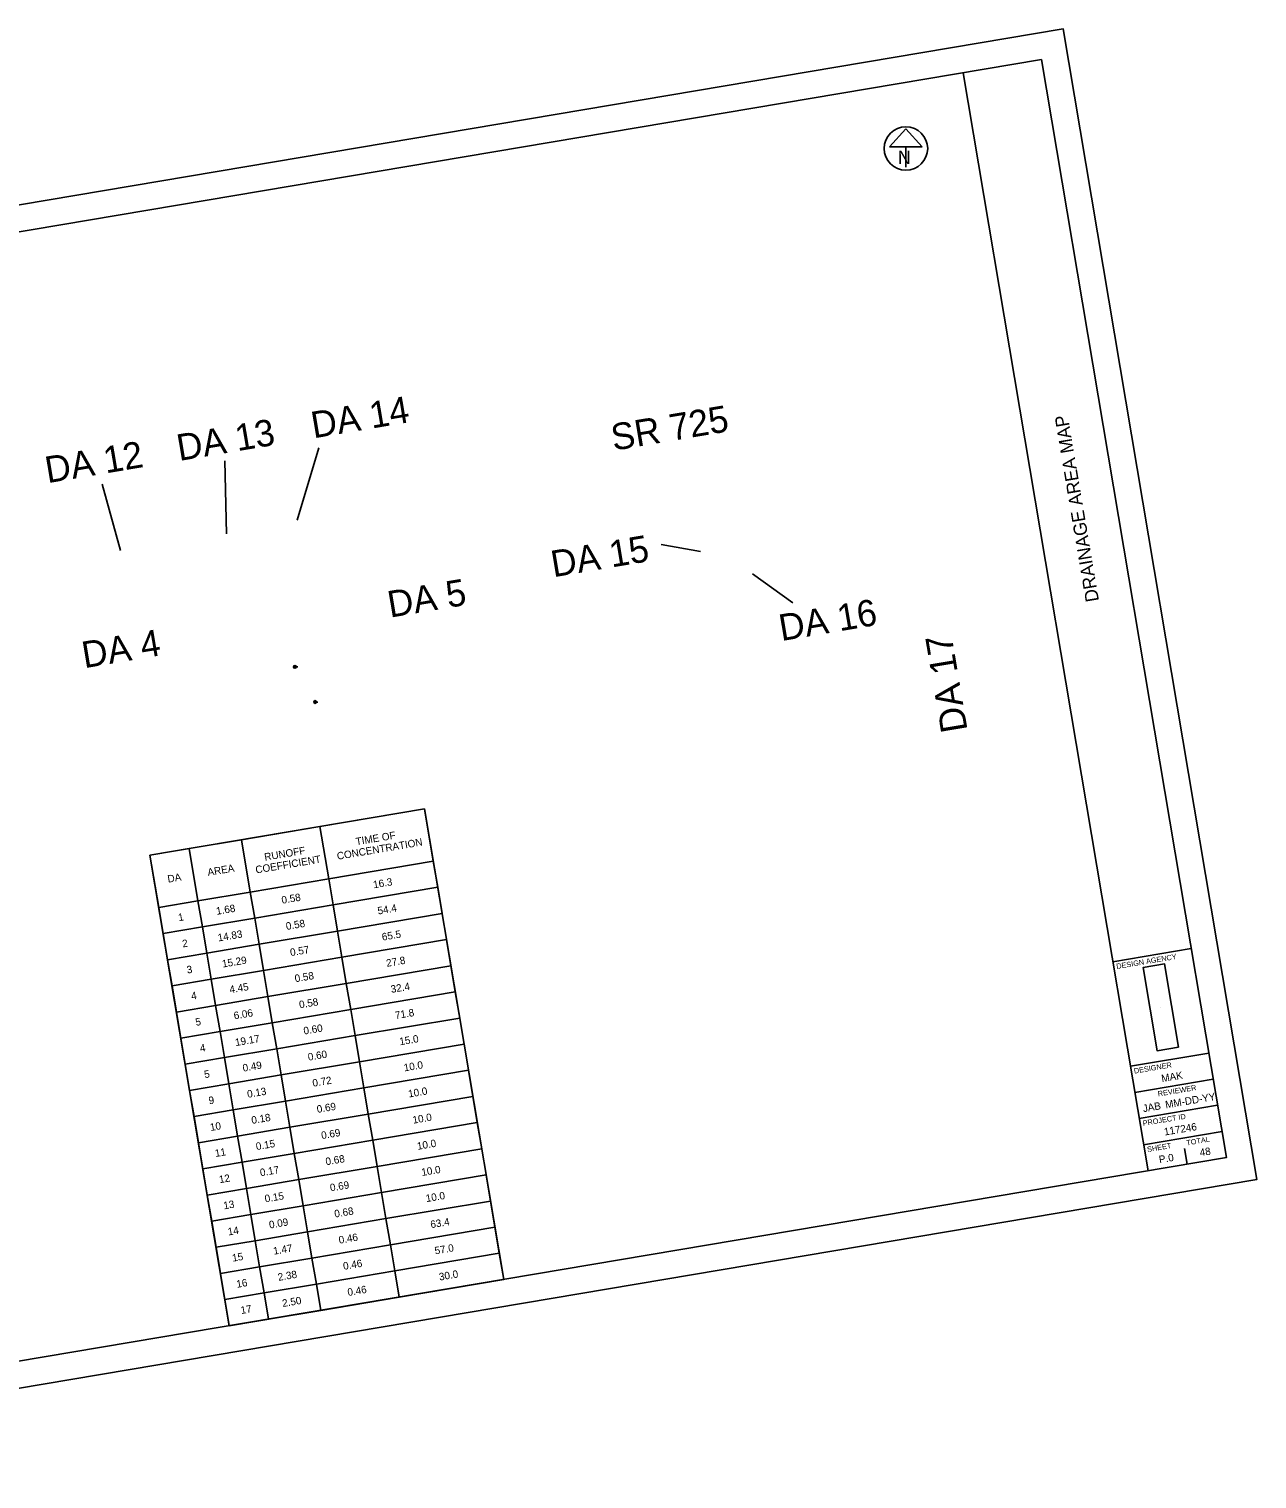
# Model space of a CAD drawing. Extents: x 1385694 to 1389997, y 599492 to 605799.
# Drawn here: x 1387096 to 1389413, y 603064 to 605799 of the extents above; entities that cross this region are included whole.
import ezdxf

# ---------------------------------------------------------------- set-up
doc = ezdxf.new("R2010")
doc.units = 0
for name, color, linetype in [('_CIVIL_CONSTRUCTION', 7, 'Continuous'), ('DR_X_Storm_Sewer', 7, 'Continuous'), ('GK_Drainage_Nodes', 7, 'Continuous'), ('RS_Raster1', 7, 'Continuous'), ('SC_Scratch1', 7, 'Continuous')]:
    doc.layers.add(name, color=color, linetype=linetype)

msp = doc.modelspace()

# ---------------------------------------------------------------- linework, layer by layer
at = {"layer": '_CIVIL_CONSTRUCTION'}
for p, q in [((1389231.2, 603953.8), (1389231.2, 603953.8)), ((1389281.1, 603658), (1389276.1, 603687.6)), ((1389241.2, 603669), (1389241.2, 603669))]:
    msp.add_line(p, q, dxfattribs=at)
at = {"layer": 'DR_X_Storm_Sewer'}
for p, q in [((1389207.1, 603645.5), (1388858.1, 605716.3)), ((1389140.6, 604040), (1389288.6, 604064.9)), ((1389173.9, 603842.7), (1389321.8, 603867.7)), ((1389182.2, 603793.4), (1389330.1, 603818.4)), ((1389190.5, 603744.1), (1389338.4, 603769.1)), ((1389198.8, 603694.8), (1389346.7, 603719.8))]:
    msp.add_line(p, q, dxfattribs=at)
msp.add_lwpolyline([(1385850.5, 605209.5), (1389006, 605741.3), (1389355, 603670.5), (1386199.5, 603138.7)], close=True, dxfattribs=at)
at = {"layer": 'GK_Drainage_Nodes'}
msp.add_lwpolyline([(1387324.4, 604240.9), (1387842.1, 604328.2), (1387991.7, 603440.7), (1387474, 603353.4)], close=True, dxfattribs=at)
msp.add_circle((1388750.4, 605573.5), 41, dxfattribs=at)
at = {"layer": 'RS_Raster1'}
for p, q in [((1388750.4, 605610.9), (1388719.7, 605576.7)), ((1388781.2, 605576.7), (1388750.4, 605610.9)), ((1388719.7, 605576.7), (1388781.2, 605576.7)), ((1388750.4, 605576.7), (1388750.4, 605538.1)), ((1387643.1, 605009.3), (1387602.2, 604872.7)), ((1387465.6, 604984.4), (1387468.5, 604846.9)), ((1387234.1, 604940.2), (1387268.8, 604815.2)), ((1388288.6, 604826.9), (1388363, 604813.7)), ((1388537.2, 604716.9), (1388460.7, 604771.4)), ((1387595.2, 604595.8), (1387600.4, 604595.8)), ((1387597.8, 604595.8), (1387603.2, 604595.8)), ((1387633.3, 604529.7), (1387638.5, 604529.7)), ((1387635.9, 604529.7), (1387641.2, 604529.7))]:
    msp.add_line(p, q, dxfattribs=at)
for points in [[(1387644.9, 604294.9), (1387842.1, 604328.2), (1387858.7, 604229.6), (1387661.5, 604196.3)], [(1387497, 604270), (1387644.9, 604294.9), (1387661.5, 604196.3), (1387513.6, 604171.4)], [(1387398.4, 604253.4), (1387497, 604270), (1387513.6, 604171.4), (1387415, 604154.8)], [(1387324.4, 604240.9), (1387398.4, 604253.4), (1387415, 604154.8), (1387341, 604142.3)], [(1387661.5, 604196.3), (1387858.7, 604229.6), (1387867.1, 604180.3), (1387669.8, 604147)], [(1387513.6, 604171.4), (1387661.5, 604196.3), (1387669.8, 604147), (1387521.9, 604122.1)], [(1387669.8, 604147), (1387867.1, 604180.3), (1387875.4, 604131), (1387678.1, 604097.7)], [(1387341, 604142.3), (1387415, 604154.8), (1387423.3, 604105.5), (1387349.4, 604093)], [(1387415, 604154.8), (1387513.6, 604171.4), (1387521.9, 604122.1), (1387423.3, 604105.5)], [(1387521.9, 604122.1), (1387669.8, 604147), (1387678.1, 604097.7), (1387530.2, 604072.8)], [(1387423.3, 604105.5), (1387521.9, 604122.1), (1387530.2, 604072.8), (1387431.6, 604056.2)], [(1387678.1, 604097.7), (1387875.4, 604131), (1387883.7, 604081.7), (1387686.5, 604048.4)], [(1387349.4, 604093), (1387423.3, 604105.5), (1387431.6, 604056.2), (1387357.7, 604043.7)], [(1387530.2, 604072.8), (1387678.1, 604097.7), (1387686.5, 604048.4), (1387538.5, 604023.5)], [(1387431.6, 604056.2), (1387530.2, 604072.8), (1387538.5, 604023.5), (1387439.9, 604006.9)], [(1387686.5, 604048.4), (1387883.7, 604081.7), (1387892, 604032.4), (1387694.8, 603999.1)], [(1387357.7, 604043.7), (1387431.6, 604056.2), (1387439.9, 604006.9), (1387366, 603994.4)], [(1387538.5, 604023.5), (1387686.5, 604048.4), (1387694.8, 603999.1), (1387546.9, 603974.2)], [(1387439.9, 604006.9), (1387538.5, 604023.5), (1387546.9, 603974.2), (1387448.2, 603957.6)], [(1387694.8, 603999.1), (1387892, 604032.4), (1387900.3, 603983), (1387703.1, 603949.8)], [(1389264.7, 603878.8), (1389238.3, 604035.7), (1389197.7, 604028.8), (1389224.1, 603872)], [(1387366, 603994.4), (1387439.9, 604006.9), (1387448.2, 603957.6), (1387374.3, 603945.1)], [(1387546.9, 603974.2), (1387694.8, 603999.1), (1387703.1, 603949.8), (1387555.2, 603924.9)], [(1387703.1, 603949.8), (1387900.3, 603983), (1387908.6, 603933.7), (1387711.4, 603900.5)], [(1387374.3, 603945.1), (1387448.2, 603957.6), (1387456.6, 603908.3), (1387382.6, 603895.8)], [(1387448.2, 603957.6), (1387546.9, 603974.2), (1387555.2, 603924.9), (1387456.6, 603908.3)], [(1387555.2, 603924.9), (1387703.1, 603949.8), (1387711.4, 603900.5), (1387563.5, 603875.6)], [(1387711.4, 603900.5), (1387908.6, 603933.7), (1387916.9, 603884.4), (1387719.7, 603851.2)], [(1387382.6, 603895.8), (1387456.6, 603908.3), (1387464.9, 603859), (1387390.9, 603846.5)], [(1387456.6, 603908.3), (1387555.2, 603924.9), (1387563.5, 603875.6), (1387464.9, 603859)], [(1387563.5, 603875.6), (1387711.4, 603900.5), (1387719.7, 603851.2), (1387571.8, 603826.3)], [(1387464.9, 603859), (1387563.5, 603875.6), (1387571.8, 603826.3), (1387473.2, 603809.7)], [(1387719.7, 603851.2), (1387916.9, 603884.4), (1387925.2, 603835.1), (1387728, 603801.9)], [(1387390.9, 603846.5), (1387464.9, 603859), (1387473.2, 603809.7), (1387399.2, 603797.2)], [(1387571.8, 603826.3), (1387719.7, 603851.2), (1387728, 603801.9), (1387580.1, 603777)], [(1387473.2, 603809.7), (1387571.8, 603826.3), (1387580.1, 603777), (1387481.5, 603760.3)], [(1387728, 603801.9), (1387925.2, 603835.1), (1387933.5, 603785.8), (1387736.3, 603752.6)], [(1387399.2, 603797.2), (1387473.2, 603809.7), (1387481.5, 603760.3), (1387407.5, 603747.9)], [(1387580.1, 603777), (1387728, 603801.9), (1387736.3, 603752.6), (1387588.4, 603727.7)], [(1387481.5, 603760.3), (1387580.1, 603777), (1387588.4, 603727.7), (1387489.8, 603711)], [(1387736.3, 603752.6), (1387933.5, 603785.8), (1387941.8, 603736.5), (1387744.6, 603703.3)], [(1387407.5, 603747.9), (1387481.5, 603760.3), (1387489.8, 603711), (1387415.8, 603698.6)], [(1387588.4, 603727.7), (1387736.3, 603752.6), (1387744.6, 603703.3), (1387596.7, 603678.4)], [(1387744.6, 603703.3), (1387941.8, 603736.5), (1387950.2, 603687.2), (1387752.9, 603654)], [(1387415.8, 603698.6), (1387489.8, 603711), (1387498.1, 603661.7), (1387424.1, 603649.3)], [(1387489.8, 603711), (1387588.4, 603727.7), (1387596.7, 603678.4), (1387498.1, 603661.7)], [(1387596.7, 603678.4), (1387744.6, 603703.3), (1387752.9, 603654), (1387605, 603629.1)], [(1387752.9, 603654), (1387950.2, 603687.2), (1387958.5, 603637.9), (1387761.2, 603604.7)], [(1387424.1, 603649.3), (1387498.1, 603661.7), (1387506.4, 603612.4), (1387432.5, 603600)], [(1387498.1, 603661.7), (1387596.7, 603678.4), (1387605, 603629.1), (1387506.4, 603612.4)], [(1387506.4, 603612.4), (1387605, 603629.1), (1387613.3, 603579.7), (1387514.7, 603563.1)], [(1387605, 603629.1), (1387752.9, 603654), (1387761.2, 603604.7), (1387613.3, 603579.7)], [(1387761.2, 603604.7), (1387958.5, 603637.9), (1387966.8, 603588.6), (1387769.6, 603555.4)], [(1387432.5, 603600), (1387506.4, 603612.4), (1387514.7, 603563.1), (1387440.8, 603550.7)], [(1387613.3, 603579.7), (1387761.2, 603604.7), (1387769.6, 603555.4), (1387621.6, 603530.4)], [(1387514.7, 603563.1), (1387613.3, 603579.7), (1387621.6, 603530.4), (1387523, 603513.8)], [(1387769.6, 603555.4), (1387966.8, 603588.6), (1387975.1, 603539.3), (1387777.9, 603506.1)], [(1387440.8, 603550.7), (1387514.7, 603563.1), (1387523, 603513.8), (1387449.1, 603501.4)], [(1387621.6, 603530.4), (1387769.6, 603555.4), (1387777.9, 603506.1), (1387629.9, 603481.1)], [(1387523, 603513.8), (1387621.6, 603530.4), (1387629.9, 603481.1), (1387531.3, 603464.5)], [(1387777.9, 603506.1), (1387975.1, 603539.3), (1387983.4, 603490), (1387786.2, 603456.8)], [(1387449.1, 603501.4), (1387523, 603513.8), (1387531.3, 603464.5), (1387457.4, 603452.1)], [(1387629.9, 603481.1), (1387777.9, 603506.1), (1387786.2, 603456.8), (1387638.3, 603431.8)], [(1387457.4, 603452.1), (1387531.3, 603464.5), (1387539.6, 603415.2), (1387465.7, 603402.8)], [(1387531.3, 603464.5), (1387629.9, 603481.1), (1387638.3, 603431.8), (1387539.6, 603415.2)], [(1387786.2, 603456.8), (1387983.4, 603490), (1387991.7, 603440.7), (1387794.5, 603407.5)], [(1387638.3, 603431.8), (1387786.2, 603456.8), (1387794.5, 603407.5), (1387646.6, 603382.5)], [(1387465.7, 603402.8), (1387539.6, 603415.2), (1387548, 603365.9), (1387474, 603353.4)], [(1387539.6, 603415.2), (1387638.3, 603431.8), (1387646.6, 603382.5), (1387548, 603365.9)]]:
    msp.add_lwpolyline(points, close=True, dxfattribs=at)
for centre, radius in [((1388750.4, 605573.5), 41), ((1387597.8, 604595.8), 2.6), ((1387635.9, 604529.7), 2.6)]:
    msp.add_circle(centre, radius, dxfattribs=at)
at = {"layer": 'SC_Scratch1'}
msp.add_lwpolyline([(1386059.9, 603064.4), (1389412.6, 603629.5), (1389047, 605798.9), (1385694.3, 605233.8)], close=True, dxfattribs=at)

# ---------------------------------------------------------------- texts
at = {"layer": '_CIVIL_CONSTRUCTION'}
for s, height, rotation, p in [('DRAINAGE AREA MAP', 25, 99.5661, (1389114.7, 604720.6)), ('DESIGN AGENCY', 10, 9.5661, (1389148.1, 604026)), ('DESIGNER', 10, 9.5661, (1389181.3, 603828.8)), ('MAK', 14, 9.5661, (1389233.4, 603812.7)), ('REVIEWER', 10, 9.5661, (1389226.3, 603785.7)), ('MM-DD-YY', 14, 9.5661, (1389240.7, 603763.3)), ('JAB', 14, 9.5661, (1389198.4, 603756.1)), ('PROJECT ID', 10, 9.5661, (1389197.9, 603730.2)), ('117246', 14, 9.5661, (1389238.4, 603712.1)), ('TOTAL', 10, 9.5661, (1389280.2, 603693.3)), ('SHEET', 10, 9.5661, (1389206.2, 603680.9)), ('48', 14, 9.5661, (1389305.7, 603672.8)), ('P.0', 14, 9.5661, (1389228.8, 603659.8))]:
    msp.add_text(s, height=height, rotation=rotation, dxfattribs=at).set_placement(p)
at = {"layer": 'RS_Raster1'}
for s, height, p in [('N', 25, (1388735.3, 605544.4)), ('P.0', 0.328, (1387597.5, 604594.9)), ('3', 0.328, (1387597.7, 604596.5)), ('Drawing-2', 0.328, (1387601.1, 604596.5)), ('1:100', 0.328, (1387601.1, 604594.9)), ('2', 0.328, (1387635.7, 604530.3)), ('Drawing-1', 0.328, (1387639.1, 604530.3)), ('P.0', 0.328, (1387635.6, 604528.7)), ('1:100', 0.328, (1387639.1, 604528.7))]:
    msp.add_text(s, height=height, dxfattribs=at).set_placement(p)
for s, height, rotation, p in [('DA 14', 50, 9.5661, (1387632.9, 605026.8)), ('SR 725', 50, 9.5661, (1388198.8, 605003.5)), ('DA 13', 50, 9.5661, (1387379.5, 604984.1)), ('DA 12', 50, 9.5661, (1387131.1, 604942.2)), ('DA 15', 50, 9.5661, (1388085.3, 604764.8)), ('DA 5', 50, 9.5661, (1387777.2, 604688.6)), ('DA 16', 50, 9.5661, (1388515.4, 604644.5)), ('DA 4', 50, 9.5661, (1387200.5, 604593.3)), ('DA 17', 50, 99.5661, (1388866.8, 604476.6)), ('TIME OF', 14, 9.5661, (1387713.7, 604259.4)), ('RUNOFF', 14, 9.5661, (1387541.3, 604230.3)), ('CONCENTRATION', 14, 9.5661, (1387678.3, 604232.1)), ('COEFFICIENT', 14, 9.5661, (1387524.6, 604206.2)), ('DA', 14, 9.5661, (1387358.7, 604188.9)), ('AREA', 14, 9.5661, (1387434.1, 604201.6)), ('16.3', 14, 9.5661, (1387746.6, 604178.2)), ('1.68', 14, 9.5661, (1387450.4, 604128.3)), ('0.58', 14, 9.5661, (1387573.7, 604149.1)), ('54.4', 14, 9.5661, (1387754.9, 604128.9)), ('1', 14, 9.5661, (1387378.8, 604116.2)), ('0.58', 14, 9.5661, (1387582, 604099.8)), ('14.83', 14, 9.5661, (1387453.5, 604078.1)), ('65.5', 14, 9.5661, (1387763, 604079.6)), ('2', 14, 9.5661, (1387386.5, 604066.8)), ('0.57', 14, 9.5661, (1387589.9, 604050.4)), ('15.29', 14, 9.5661, (1387461.6, 604028.8)), ('27.8', 14, 9.5661, (1387771.2, 604030.2)), ('3', 14, 9.5661, (1387394.9, 604017.5)), ('0.58', 14, 9.5661, (1387598.6, 604001.2)), ('4', 14, 9.5661, (1387403.2, 603968.2)), ('4.45', 14, 9.5661, (1387475.5, 603980.4)), ('32.4', 14, 9.5661, (1387779.8, 603981)), ('0.58', 14, 9.5661, (1387606.9, 603951.9)), ('5', 14, 9.5661, (1387411.3, 603918.9)), ('6.06', 14, 9.5661, (1387483.6, 603931.1)), ('71.8', 14, 9.5661, (1387787.8, 603931.6)), ('19.17', 14, 9.5661, (1387486.1, 603880.8)), ('0.60', 14, 9.5661, (1387615.2, 603902.5)), ('15.0', 14, 9.5661, (1387796.1, 603882.3)), ('4', 14, 9.5661, (1387419.8, 603869.6)), ('0.49', 14, 9.5661, (1387500.4, 603832.5)), ('0.60', 14, 9.5661, (1387623.5, 603853.2)), ('10.0', 14, 9.5661, (1387804.4, 603833)), ('5', 14, 9.5661, (1387427.9, 603820.3)), ('0.72', 14, 9.5661, (1387632.1, 603804)), ('0.13', 14, 9.5661, (1387508.9, 603783.2)), ('10.0', 14, 9.5661, (1387812.7, 603783.7)), ('9', 14, 9.5661, (1387436.2, 603771)), ('0.69', 14, 9.5661, (1387640.3, 603754.7)), ('10', 14, 9.5661, (1387438.8, 603720.7)), ('0.18', 14, 9.5661, (1387516.9, 603733.9)), ('10.0', 14, 9.5661, (1387821, 603734.4)), ('0.69', 14, 9.5661, (1387648.6, 603705.3)), ('11', 14, 9.5661, (1387448.1, 603671.6)), ('0.15', 14, 9.5661, (1387525.4, 603684.6)), ('10.0', 14, 9.5661, (1387829.3, 603685.1)), ('0.17', 14, 9.5661, (1387533.1, 603635.2)), ('0.68', 14, 9.5661, (1387656.8, 603656)), ('10.0', 14, 9.5661, (1387837.6, 603635.8)), ('12', 14, 9.5661, (1387455.8, 603622.2)), ('0.15', 14, 9.5661, (1387542, 603586)), ('0.69', 14, 9.5661, (1387665.2, 603606.7)), ('10.0', 14, 9.5661, (1387845.9, 603586.5)), ('13', 14, 9.5661, (1387464.1, 603572.9)), ('0.68', 14, 9.5661, (1387673.4, 603557.4)), ('0.09', 14, 9.5661, (1387550.2, 603536.7)), ('63.4', 14, 9.5661, (1387854.6, 603537.3)), ('14', 14, 9.5661, (1387472.4, 603523.6)), ('0.46', 14, 9.5661, (1387681.6, 603508.1)), ('15', 14, 9.5661, (1387480.6, 603474.2)), ('1.47', 14, 9.5661, (1387558.1, 603487.3)), ('57.0', 14, 9.5661, (1387862.5, 603487.9)), ('0.46', 14, 9.5661, (1387689.9, 603458.8)), ('16', 14, 9.5661, (1387488.6, 603424.9)), ('2.38', 14, 9.5661, (1387566.8, 603438)), ('30.0', 14, 9.5661, (1387870.8, 603438.6)), ('2.50', 14, 9.5661, (1387575, 603388.7)), ('0.46', 14, 9.5661, (1387698.2, 603409.5)), ('17', 14, 9.5661, (1387496.6, 603375.5))]:
    msp.add_text(s, height=height, rotation=rotation, dxfattribs=at).set_placement(p)

doc.saveas('drawing.dxf')
